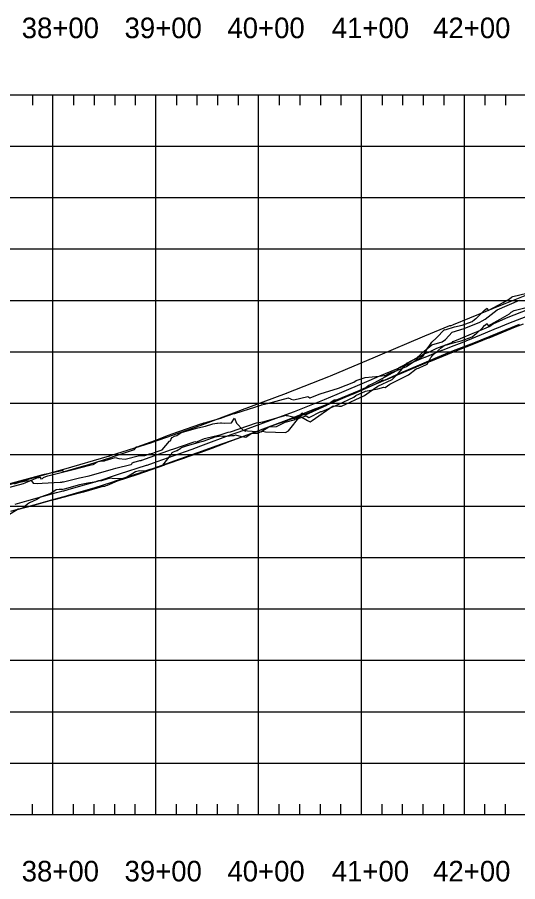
# Model space of a CAD drawing. Extents: x 704797 to 712284, y 374940 to 376945.
# Drawn here: x 710899 to 711386, y 375160 to 376001 of the extents above; entities that cross this region are included whole.
import ezdxf

# ---------------------------------------------------------------- set-up
doc = ezdxf.new("R2010")
doc.units = 0
for name, color, linetype in [('10', 7, 'Continuous'), ('12', 7, 'Continuous'), ('13', 7, 'Continuous'), ('61', 7, 'Continuous'), ('63', 7, 'Continuous'), ('Existing', 7, 'Continuous')]:
    doc.layers.add(name, color=color, linetype=linetype)

msp = doc.modelspace()

# ---------------------------------------------------------------- linework, layer by layer
at = {"layer": '10'}
for points in [[(711395.06, 375716.31), (711375.98, 375708.74), (711361.85, 375702.63), (711358.48, 375700.14), (711346.85, 375695.38), (711340.37, 375692.49), (711329.63, 375688.11), (711322.41, 375685.32), (711321.97, 375685.1), (711321.79, 375684.52), (711320.57, 375683.8), (711306.63, 375678.69), (711298.15, 375674.56), (711294.47, 375673.39), (711293.09, 375672.2), (711273.16, 375661.51), (711270.08, 375659.77), (711267.84, 375657.05), (711245.72, 375644.93), (711245.03, 375644.56), (711240.88, 375642.64), (711238.18, 375640.76), (711230.95, 375637.39), (711208.95, 375628.43), (711206.97, 375628.56), (711199.57, 375623.37), (711178.93, 375613.85), (711175.62, 375615.8), (711172.19, 375611.49), (711167.8, 375609.04), (711159.11, 375606.84), (711150.82, 375602.53), (711143.47, 375602.31), (711136.65, 375597.9), (711132.16, 375595.88), (711126.95, 375596.06), (711121.23, 375592.01), (711117.08, 375592.94), (711111.6, 375594.34), (711111.29, 375594.52), (711109.64, 375593.9), (711107.61, 375593.74), (711105.2, 375593.38), (711099.61, 375593.01), (711098.5, 375593.15), (711096.78, 375593.39), (711095.4, 375593.2), (711093.67, 375592.98), (711092.95, 375592.86), (711091.06, 375592.5), (711088.52, 375591.59), (711079.46, 375588.28), (711075.5, 375587.41), (711063.24, 375583.73), (711058.25, 375581.95), (711057.93, 375581.61), (711053.96, 375578.95), (711053.87, 375579.22), (711050.62, 375577.86), (711049.18, 375577.17), (711048.59, 375576.04), (711048.25, 375574.83), (711047.31, 375574.3), (711041.5, 375566.77), (711039.83, 375564.79), (711033.82, 375562.86), (711030.69, 375561.69), (711027.75, 375560.96), (711022.98, 375559.57), (711017.83, 375559.7), (711013.9, 375558.74), (711004.55, 375553.02), (711000.7, 375552.08), (710991.25, 375552.12), (710989.65, 375552.61), (710989.29, 375552.5), (710981.01, 375549.86), (710977.86, 375550), (710977.02, 375549.73), (710976.06, 375549.48), (710976.03, 375549.47), (710974.67, 375548.8), (710974.3, 375548.58), (710974.06, 375548.62), (710973.74, 375548.68), (710967.55, 375547.87), (710959.49, 375545.99), (710944.43, 375541.98), (710942.84, 375541.51), (710942.59, 375541.39), (710942.57, 375541.35), (710942.46, 375541.45), (710939.77, 375541.42), (710936.97, 375541.39), (710931.6, 375537.6), (710921.46, 375534.22), (710917.95, 375531.87), (710910.98, 375528.55), (710909.09, 375527.4), (710904.54, 375523.57), (710904.15, 375523.34), (710903.33, 375523.06), (710899.81, 375522.54), (710890.51, 375516.7)], [(710896.37, 375547.23), (710901.24, 375548.79), (710907.58, 375549.96), (710907.95, 375549.99), (710912.5, 375550.31), (710913.73, 375548.73), (710914.51, 375547.66), (710918.45, 375547.33), (710923.29, 375547.83), (710940.85, 375548.87), (710942.19, 375548.86), (710942.84, 375548.99), (710943.47, 375549.06), (710943.96, 375549.11), (710959.48, 375553), (710968.83, 375554.71), (710992.64, 375561.82), (710994.98, 375562.28), (711009.52, 375566.03), (711009.54, 375566.03), (711009.55, 375566.04), (711009.58, 375566.05), (711010.53, 375566.55), (711010.76, 375567.2), (711011.07, 375567.92), (711011.17, 375567.93), (711011.21, 375567.94), (711011.54, 375567.97), (711011.68, 375567.99), (711012.4, 375568.07), (711012.67, 375568.12), (711018.19, 375569.66), (711018.8, 375569.79), (711019.16, 375569.87), (711019.41, 375569.92), (711019.73, 375569.98), (711019.93, 375570.01), (711019.97, 375570.02), (711020.08, 375570.03), (711020.23, 375570.08), (711048.96, 375580.34), (711050.35, 375580.87), (711070.1, 375587.67), (711071.7, 375588.16), (711073.41, 375587.77), (711073.7, 375587.95), (711074.19, 375588.18), (711081.09, 375591.32), (711090.57, 375593.31), (711092.19, 375593.78), (711097.27, 375595.21), (711104.15, 375597.24), (711106.29, 375597.8), (711131.59, 375606.34), (711137.8, 375607.51), (711160.58, 375613.81), (711161.45, 375613.37), (711161.63, 375613.42), (711166.97, 375612.09), (711168.4, 375610.45), (711168.63, 375610.39), (711170.2, 375610.02), (711180, 375613.29), (711182.62, 375611.47), (711182.93, 375611.67), (711194.26, 375617.34), (711195.02, 375617.5), (711210.96, 375624.1), (711226.19, 375631.39), (711228.3, 375633), (711237.67, 375637.26), (711249.45, 375639.37), (711255.36, 375641.06), (711256.81, 375640.92), (711261.35, 375643.91), (711269.67, 375648.2), (711279.43, 375653.24), (711286.96, 375658.92), (711287.92, 375659.24), (711289.18, 375659.41), (711294.59, 375662.05), (711295.43, 375662.58), (711297.54, 375663.55), (711300.19, 375668.1), (711301.24, 375669.99), (711301.75, 375670.58), (711302.67, 375671.91), (711311.41, 375679.68), (711314.04, 375681.64), (711314.15, 375681.65), (711315.27, 375682.23), (711315.43, 375682.03), (711323.95, 375684.6), (711330.56, 375686.12), (711341.19, 375689.95), (711343.37, 375691.7), (711343.44, 375691.96), (711344.95, 375692.86), (711344.95, 375692.62), (711351.63, 375699.2), (711353.32, 375700.92), (711355.71, 375702.87), (711356.67, 375700.84), (711368.33, 375707.09), (711377.46, 375712.54), (711379.09, 375713.99), (711381.95, 375715.67), (711382.1, 375715.75), (711393.61, 375718.55)]]:
    msp.add_lwpolyline(points, dxfattribs=at)
at = {"layer": '12'}
for points in [[(710897.08, 375527.35), (710908.36, 375530.43), (710937.18, 375538.53), (710943.46, 375540.14), (710944.14, 375540.31), (710951.64, 375542.5), (710979.27, 375550.45), (710982.21, 375551.39), (710989.6, 375553.81), (710998.49, 375556.83), (711024.62, 375565.27), (711025.13, 375565.38), (711035.08, 375568.97), (711062.48, 375578.58), (711069.07, 375580.88), (711077.58, 375583.94), (711106.8, 375595.08), (711114.59, 375597.78), (711123.36, 375600.98), (711156.76, 375613.31), (711168.44, 375617.48), (711178.18, 375621.35), (711197.76, 375629.09), (711210.13, 375634.31), (711241.1, 375647.56), (711251.58, 375652.05), (711279.15, 375663.55), (711291.94, 375668.99), (711295.31, 375670.37), (711295.51, 375670.29), (711311.79, 375677.01), (711312.36, 375676.96), (711321.17, 375680.62), (711331.52, 375684.61), (711354.1, 375693.87), (711365.03, 375698.35), (711365.29, 375698.44), (711377, 375703.2), (711402.18, 375713.02)], [(710893.69, 375520.74), (710915.47, 375526.74), (710932.52, 375531.6), (710943.31, 375534.41), (710944.43, 375534.7), (710956.55, 375538.28), (710974.77, 375543.6), (710989.84, 375548.47), (711003.9, 375553.17), (711019.99, 375558.31), (711020.9, 375558.5), (711039.83, 375565.27), (711057.05, 375571.27), (711078.99, 375579.15), (711092.23, 375584.19), (711113.67, 375591.59), (711138.33, 375600.58), (711149.23, 375604.6), (711182.03, 375616.27), (711187.94, 375618.62), (711204.83, 375625.75), (711224.07, 375633.91), (711226.05, 375634.77), (711246.44, 375643.57), (711254.34, 375648.13), (711255.96, 375647.87), (711257.35, 375648.18), (711266.34, 375652.12), (711289.32, 375661.94), (711297.94, 375665.47), (711298.43, 375665.27), (711300.85, 375666.28), (711300.94, 375666.27), (711323.15, 375675.54), (711347.69, 375685.04), (711357.21, 375688.97), (711357.79, 375689.18), (711383.55, 375699.7), (711391.21, 375702.7)]]:
    msp.add_lwpolyline(points, dxfattribs=at)
at = {"layer": '13'}
msp.add_lwpolyline([(711387.06, 375702.05), (711365.47, 375693.43), (711342.44, 375683.93), (711322.95, 375676.34), (711322.75, 375676.5), (711318.86, 375674.9), (711307.26, 375670.06), (711289.66, 375662.52), (711270.52, 375654.53), (711252.28, 375646.06), (711233.02, 375638.06), (711212.95, 375629.5), (711194.32, 375622.11), (711187.97, 375619.62), (711176.11, 375614.93), (711160.34, 375608.66), (711140.28, 375601.28), (711118.88, 375593.27), (711105.61, 375588.32), (711088.05, 375581.6), (711076.63, 375577.31), (711064.98, 375573.36), (711061.68, 375572.2), (711042.56, 375565.47), (711042.17, 375565.3), (711030.14, 375560.99), (711015.08, 375555.8), (710996.28, 375549.62), (710986.32, 375545.55), (710985.02, 375544.99), (710983.69, 375544.62), (710982.21, 375544.58), (710963.51, 375538.95), (710948.06, 375535.04), (710936.1, 375531.91), (710931.13, 375530.63), (710930.77, 375530.64), (710913.53, 375525.73), (710892.38, 375520.16)], dxfattribs=at)
at = {"layer": '61'}
for p, q in [((708133.69, 375925.47), (712133.69, 375925.47)), ((710913.69, 375925.47), (710913.69, 375915.47)), ((710933.69, 375225.47), (710933.69, 375925.47)), ((710953.69, 375925.47), (710953.69, 375915.47)), ((710973.69, 375925.47), (710973.69, 375915.47)), ((710993.69, 375925.47), (710993.69, 375915.47)), ((711013.69, 375925.47), (711013.69, 375915.47)), ((711033.69, 375225.47), (711033.69, 375925.47)), ((711053.69, 375925.47), (711053.69, 375915.47)), ((711073.69, 375925.47), (711073.69, 375915.47)), ((711093.69, 375925.47), (711093.69, 375915.47)), ((711113.69, 375925.47), (711113.69, 375915.47)), ((711133.69, 375225.47), (711133.69, 375925.47)), ((711153.69, 375925.47), (711153.69, 375915.47)), ((711173.69, 375925.47), (711173.69, 375915.47)), ((711193.69, 375925.47), (711193.69, 375915.47)), ((711213.69, 375925.47), (711213.69, 375915.47)), ((711233.69, 375225.47), (711233.69, 375925.47)), ((711253.69, 375925.47), (711253.69, 375915.47)), ((711273.69, 375925.47), (711273.69, 375915.47)), ((711293.69, 375925.47), (711293.69, 375915.47)), ((711313.69, 375925.47), (711313.69, 375915.47)), ((711333.69, 375225.47), (711333.69, 375925.47)), ((711353.69, 375925.47), (711353.69, 375915.47)), ((711373.69, 375925.47), (711373.69, 375915.47)), ((708133.69, 375875.47), (712133.69, 375875.47)), ((708133.69, 375825.47), (712133.69, 375825.47)), ((708133.69, 375775.47), (712133.69, 375775.47)), ((708133.69, 375725.47), (712133.69, 375725.47)), ((708133.69, 375675.47), (712133.69, 375675.47)), ((708133.69, 375625.47), (712133.69, 375625.47)), ((708133.69, 375575.47), (712133.69, 375575.47)), ((708133.69, 375525.47), (712133.69, 375525.47)), ((708133.69, 375475.47), (712133.69, 375475.47)), ((708133.69, 375425.47), (712133.69, 375425.47)), ((708133.69, 375375.47), (712133.69, 375375.47)), ((708133.69, 375325.47), (712133.69, 375325.47)), ((708133.69, 375275.47), (712133.69, 375275.47)), ((710913.69, 375225.47), (710913.69, 375235.47)), ((710953.69, 375225.47), (710953.69, 375235.47)), ((710973.69, 375225.47), (710973.69, 375235.47)), ((710993.69, 375225.47), (710993.69, 375235.47)), ((711013.69, 375225.47), (711013.69, 375235.47)), ((711053.69, 375225.47), (711053.69, 375235.47)), ((711073.69, 375225.47), (711073.69, 375235.47)), ((711093.69, 375225.47), (711093.69, 375235.47)), ((711113.69, 375225.47), (711113.69, 375235.47)), ((711153.69, 375225.47), (711153.69, 375235.47)), ((711173.69, 375225.47), (711173.69, 375235.47)), ((711193.69, 375225.47), (711193.69, 375235.47)), ((711213.69, 375225.47), (711213.69, 375235.47)), ((711253.69, 375225.47), (711253.69, 375235.47)), ((711273.69, 375225.47), (711273.69, 375235.47)), ((711293.69, 375225.47), (711293.69, 375235.47)), ((711313.69, 375225.47), (711313.69, 375235.47)), ((711353.69, 375225.47), (711353.69, 375235.47)), ((711373.69, 375225.47), (711373.69, 375235.47)), ((708133.69, 375225.47), (712133.69, 375225.47))]:
    msp.add_line(p, q, dxfattribs=at)
at = {"layer": '63'}
for points in [[(710890.74, 375547.15), (710924.02, 375556.13), (710924.65, 375556.3), (710925.54, 375556.35), (710939.55, 375559.4), (710943.09, 375559.99), (710943.89, 375559.11), (710944.11, 375558.85), (710944.14, 375558.81), (710944.94, 375558.94), (710945.04, 375558.94), (710948.3, 375559.93), (710963.73, 375564.49), (710968.45, 375565.97), (710989.96, 375572.82), (710992.07, 375573.54), (710994.66, 375574.4), (711002.24, 375576.96), (711012.82, 375580.56), (711013.02, 375580.57), (711013.55, 375581.37), (711013.87, 375581.88), (711014.6, 375582.76), (711014.69, 375582.85), (711014.92, 375583.02), (711015.44, 375583.19), (711015.57, 375583.21), (711033.85, 375589.63), (711041.81, 375592.82), (711046.11, 375594.35), (711049.7, 375595.59), (711077.5, 375605.58), (711078.03, 375605.44), (711080.42, 375606.52), (711083.33, 375607.13), (711097.89, 375611.29), (711098.65, 375611.5), (711109.46, 375615.51), (711110.53, 375615.45), (711130.87, 375621.89), (711132.63, 375622.54), (711136.27, 375623.74), (711136.56, 375623.86), (711142.27, 375625.17), (711162.64, 375630.6), (711162.89, 375630.46), (711162.94, 375630.48), (711164.55, 375630.05), (711165, 375629.53), (711167.78, 375628.72), (711181.51, 375632.14), (711183.38, 375630.61), (711183.61, 375630.73), (711192.57, 375634.33), (711193.52, 375634.46), (711211.47, 375640.23), (711226.35, 375646.02), (711228.46, 375647.42), (711237.23, 375650.6), (711251, 375651.71), (711255.82, 375652.58), (711256.94, 375652.35), (711260.33, 375654.24), (711271.3, 375658.73), (711277.29, 375661.19), (711288.42, 375668.5), (711289.2, 375668.69), (711291.26, 375669.91), (711293.41, 375671.49), (711293.8, 375671.71), (711294.33, 375672.64), (711297.89, 375679.01), (711299.46, 375680.92), (711302.16, 375684.89), (711306.58, 375688.99), (711314.31, 375697.03), (711314.35, 375696.81), (711315.94, 375697.23), (711323.96, 375699.63), (711331.51, 375701.36), (711341.15, 375704.92), (711343.44, 375706.75), (711343.52, 375707.02), (711344.93, 375707.87), (711344.93, 375707.63), (711351.91, 375714.58), (711353.15, 375715.85), (711355.75, 375718), (711356.82, 375715.74), (711371.32, 375723.34), (711377.7, 375727.04), (711379.56, 375728.66), (711380.85, 375729.39), (711394.26, 375732.65)], [(710886.99, 375542.62), (710905.05, 375547.33), (710917.21, 375552.47), (710918.62, 375553.1), (710920.37, 375553.41), (710920.89, 375553.56), (710921.4, 375553.8), (710921.96, 375552.01), (710923.34, 375552.35), (710923.55, 375552.2), (710924.37, 375553.36), (710924.46, 375553.35), (710926.81, 375554.08), (710928.87, 375554.72), (710950.81, 375560.46), (710953.44, 375561.09), (710969.49, 375565.19), (710972.58, 375565.89), (710972.81, 375566.05), (710973.14, 375566.15), (710974.71, 375567.24), (710975.8, 375567.86), (710976.36, 375568.11), (710976.75, 375568.23), (710976.95, 375568.63), (710977.55, 375568.89), (710981.61, 375569.54), (710983.82, 375569.47), (710984.52, 375569.7), (710994.25, 375572.79), (710997.87, 375571.73), (711003.76, 375571.23), (711017.88, 375574.8), (711022.96, 375574.72), (711027.58, 375576.12), (711030.67, 375576.92), (711034.03, 375578.2), (711039.84, 375580.13), (711047.08, 375588.74), (711048.21, 375589.17), (711048.65, 375590.7), (711049.49, 375592.22), (711051.97, 375593.36), (711054.03, 375594.2), (711054.07, 375594.06), (711058.47, 375597.02), (711058.59, 375597.1), (711058.6, 375597.1), (711058.62, 375597.11), (711074.52, 375601.62), (711081.94, 375603.09), (711088.97, 375605.46), (711092.99, 375606.1), (711093.51, 375606.17), (711096.51, 375606.45), (711097.58, 375606.41), (711100.17, 375606), (711107.4, 375606.26), (711110.3, 375611.02), (711112.06, 375606.23), (711118.32, 375599.48), (711118.72, 375599.16), (711120.83, 375598.41), (711121.68, 375598.9), (711122.83, 375598.65), (711136.17, 375597.79), (711137.27, 375598.3), (711140.23, 375597.71), (711159.71, 375597.16), (711162.59, 375598.75), (711173.89, 375612.93), (711181.11, 375608.67), (711183.61, 375607.48), (711185.66, 375608.53), (711206.19, 375622.86), (711211.63, 375622.49), (711214.35, 375622.5), (711236.43, 375632.86), (711241.23, 375636.34), (711249.59, 375642.16), (711263.45, 375648.54), (711269.22, 375654.37), (711278.25, 375664.73), (711287.44, 375669.46), (711294.66, 375676.12), (711302.18, 375682.29), (711312.17, 375685.2), (711315.21, 375687.58), (711321.86, 375694.6), (711333.55, 375698.22), (711348.72, 375704.14), (711350.99, 375705.63), (711353.8, 375707.27), (711365.73, 375716.22), (711387.26, 375725.69)]]:
    msp.add_lwpolyline(points, dxfattribs=at)
at = {"layer": 'Existing'}
msp.add_lwpolyline([(710891.16, 375546.43), (710899.8, 375548.64), (710901.91, 375549.23), (710943.06, 375560.97), (710943.67, 375561.13), (710943.73, 375561.14), (710944.4, 375561.34), (710988.54, 375574.26), (710989.15, 375574.45), (710989.71, 375574.64), (711029.73, 375587.44), (711029.77, 375587.44), (711030.6, 375587.74), (711076.7, 375603.8), (711114.71, 375618.22), (711115.27, 375618.43), (711160.64, 375635.24), (711160.98, 375635.36), (711161.26, 375635.48), (711202, 375651.45), (711203.67, 375652.11), (711247.16, 375670.65), (711249.55, 375671.64), (711251.82, 375672.69), (711293.1, 375689.94), (711295.36, 375690.91), (711319.51, 375700.97), (711319.88, 375701.12), (711320.29, 375700.77), (711323.21, 375701.91), (711370.72, 375721.51), (711373.27, 375722.53), (711412.4, 375737.96)], dxfattribs=at)

# ---------------------------------------------------------------- texts
at = {"layer": '61'}
for s, p in [('38+00', (710903.32, 375980.47)), ('39+00', (711003.32, 375980.47)), ('40+00', (711103.32, 375980.47)), ('41+00', (711204.77, 375980.47)), ('42+00', (711303.32, 375980.47)), ('38+00', (710903.32, 375160.47)), ('39+00', (711003.32, 375160.47)), ('40+00', (711103.32, 375160.47)), ('41+00', (711204.77, 375160.47)), ('42+00', (711303.32, 375160.47))]:
    msp.add_text(s, height=20, dxfattribs=at).set_placement(p)

doc.saveas('drawing.dxf')
